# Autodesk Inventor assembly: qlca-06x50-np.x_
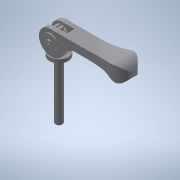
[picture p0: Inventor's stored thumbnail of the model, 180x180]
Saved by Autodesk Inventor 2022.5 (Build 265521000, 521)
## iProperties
Part Number: qlca-06x50-np.x_
Material: 一般
Document SubType Name: Assembly
Designer: ImaoCorp
Sending System: SOLIDWORKS 2017-2017317
MC: AMD64
MC_MODEL: Intel64 Family 6 Model 60 Stepping 3, GenuineIntel
OS: Windows_NT
FRU: Parasolid Version 29.0, build 201,  4-17-2017
FORMAT: text
GUISE: transmit
KEY: qlca-06x50-np
FILE: qlca-06x50-np.x_t
DATE: Wed Sep 04 15:47:49 2019
Author: ImaoCorp
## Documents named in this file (4)
- X:\14_SW2022-Inv2022\00_全2023-1023新製品(TCC)まで\q\qlca-06x50-np\QLCA-06X50-NP.iam
- X:\14_SW2022-Inv2022\00_全2023-1023新製品(TCC)まで\q\qlca-06x50-np\qlca-06x50-np_01.ipt
- X:\14_SW2022-Inv2022\00_全2023-1023新製品(TCC)まで\q\qlca-06x50-np\qlca-06x50-np_02.ipt
- X:\14_SW2022-Inv2022\00_全2023-1023新製品(TCC)まで\q\qlca-06x50-np\qlca-06x50-np_03.ipt
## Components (3 placed, 3 different names)
1. qlca-06x50-np_01
2. qlca-06x50-np_02
3. qlca-06x50-np_03
